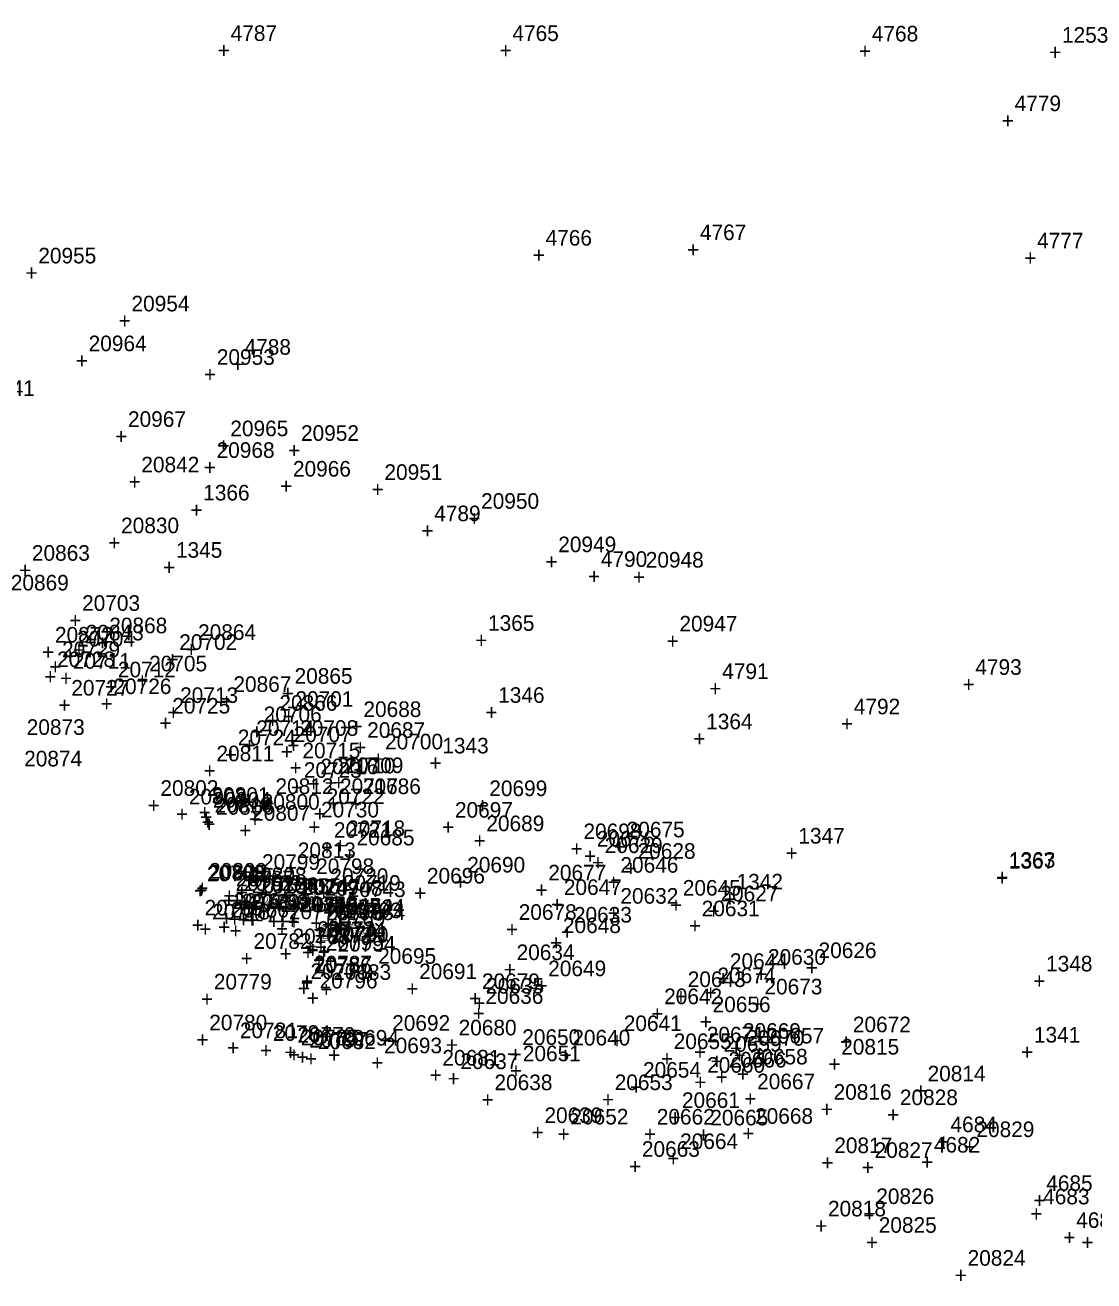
# Model space of a CAD drawing. Extents: x 1036751 to 1042192, y 772604 to 785439.
# Drawn here: x 1037673.8 to 1037845.1, y 780539.3 to 780740.6 of the extents above; entities that cross this region are included whole.
import ezdxf

# ---------------------------------------------------------------- set-up
doc = ezdxf.new("R2010")
doc.units = 0
for name, color, linetype in [('S_Buildings', 7, 'Continuous'), ('S_Buildings_Attachments', 7, 'Continuous'), ('S_Buildings_SillElevation', 7, 'Continuous'), ('S_Buildings_Steps_Brick', 7, 'Continuous'), ('S_Ground_Elevation', 7, 'Continuous'), ('S_Ground_LevelString', 7, 'Continuous'), ('S_Property_FlagPole', 7, 'Continuous'), ('S_Property_Lawn', 7, 'Continuous'), ('S_Property_Light', 7, 'Continuous'), ('S_Property_Mailbox', 7, 'Continuous'), ('S_Property_Planter', 7, 'Continuous'), ('S_Property_StoneWall', 7, 'Continuous'), ('S_RetWall_Top', 7, 'Continuous'), ('S_Roadway_Centerline', 7, 'Continuous'), ('S_Roadway_Drive_Paved', 7, 'Continuous'), ('S_Roadway_Edge_Pavement', 7, 'Continuous'), ('S_Trees_Stump', 7, 'Continuous'), ('S_Trees_TreeLine', 7, 'Continuous'), ('S_Utilities_Pole_Brace3', 7, 'Continuous'), ('S_Utilities_Pole_Power', 7, 'Continuous')]:
    doc.layers.add(name, color=color, linetype=linetype)

msp = doc.modelspace()

# ---------------------------------------------------------------- texts
at = {"layer": 'S_Buildings'}
for s, p in [('20803', (1037700.03, 780615.67)), ('20804', (1037703.89, 780615.16)), ('+', (1037697.96, 780612.92)), ('+', (1037701.83, 780612.41)), ('20805', (1037703.15, 780603.46)), ('+', (1037701.08, 780600.71))]:
    msp.add_text(s, height=2.5, dxfattribs=at).set_placement(p)
at = {"layer": 'S_Buildings_Attachments'}
for s, p in [('20768', (1037702.93, 780603.35)), ('20767', (1037707.59, 780602.54)), ('+', (1037700.87, 780600.6)), ('+', (1037705.53, 780599.79)), ('20765', (1037702.54, 780597.87)), ('20766', (1037706.77, 780597.54)), ('+', (1037700.48, 780595.12)), ('+', (1037704.71, 780594.79))]:
    msp.add_text(s, height=2.5, dxfattribs=at).set_placement(p)
at = {"layer": 'S_Buildings_SillElevation'}
for s, p in [('20810', (1037704.15, 780614.36)), ('+', (1037702.09, 780611.61))]:
    msp.add_text(s, height=2.5, dxfattribs=at).set_placement(p)
at = {"layer": 'S_Buildings_Steps_Brick'}
for s, p in [('20762', (1037707.52, 780601.81)), ('20763', (1037708.85, 780601.81)), ('20764', (1037710.08, 780601.42)), ('20756', (1037711.5, 780601.48)), ('20754', (1037711.52, 780601.39)), ('20755', (1037715.11, 780601.34)), ('20749', (1037717.99, 780601.14)), ('20747', (1037718.25, 780601.21)), ('20748', (1037721.79, 780601.02)), ('20743', (1037725.49, 780600.82)), ('+', (1037705.46, 780599.06)), ('+', (1037706.79, 780599.06)), ('20761', (1037707.15, 780598.93)), ('+', (1037708.02, 780598.67)), ('20760', (1037708.45, 780598.83)), ('+', (1037709.44, 780598.73)), ('+', (1037709.46, 780598.64)), ('20759', (1037709.88, 780598.78)), ('20758', (1037709.89, 780598.73)), ('20757', (1037711.26, 780598.69)), ('20753', (1037711.38, 780598.66)), ('+', (1037713.05, 780598.59)), ('20752', (1037714.73, 780598.43)), ('+', (1037716.19, 780598.46)), ('20751', (1037716.21, 780598.44)), ('20750', (1037717.7, 780598.46)), ('20746', (1037717.97, 780598.35)), ('20745', (1037721.55, 780598.16)), ('+', (1037715.93, 780598.39)), ('+', (1037719.73, 780598.28)), ('+', (1037723.43, 780598.07)), ('20744', (1037725.31, 780598.01)), ('+', (1037705.09, 780596.18)), ('+', (1037706.39, 780596.08)), ('+', (1037707.82, 780596.03)), ('+', (1037707.83, 780595.98)), ('+', (1037709.2, 780595.94)), ('+', (1037709.32, 780595.91)), ('+', (1037712.67, 780595.68)), ('+', (1037714.15, 780595.69)), ('+', (1037715.64, 780595.71)), ('+', (1037715.91, 780595.6)), ('+', (1037719.49, 780595.41)), ('+', (1037723.25, 780595.26))]:
    msp.add_text(s, height=2.5, dxfattribs=at).set_placement(p)
at = {"layer": 'S_Ground_Elevation'}
for s, p in [('4787', (1037706.73, 780738.07)), ('4765', (1037751.91, 780738.06)), ('4768', (1037809.54, 780737.99)), ('+', (1037704.67, 780735.32)), ('+', (1037749.85, 780735.31)), ('+', (1037807.48, 780735.24)), ('4779', (1037832.44, 780726.82)), ('+', (1037830.38, 780724.07)), ('4766', (1037757.23, 780705.26)), ('4767', (1037781.97, 780706.14)), ('4777', (1037836.04, 780704.81)), ('+', (1037779.91, 780703.39)), ('+', (1037755.17, 780702.51)), ('+', (1037833.98, 780702.06)), ('20964', (1037683.96, 780688.33)), ('4788', (1037708.96, 780687.77)), ('+', (1037681.9, 780685.58)), ('+', (1037706.9, 780685.02)), ('20965', (1037706.68, 780674.7)), ('20968', (1037704.48, 780671.23)), ('+', (1037704.62, 780671.95)), ('+', (1037702.42, 780668.48)), ('20966', (1037716.72, 780668.23)), ('+', (1037714.66, 780665.48)), ('4789', (1037739.37, 780661.08)), ('+', (1037737.31, 780658.33)), ('4790', (1037766.09, 780653.75)), ('+', (1037764.03, 780651)), ('20872', (1037678.56, 780641.62)), ('20704', (1037682.09, 780640.99)), ('+', (1037676.5, 780638.87)), ('20729', (1037679.7, 780639.28)), ('20728', (1037678.9, 780637.69)), ('+', (1037680.02, 780638.24)), ('20705', (1037693.66, 780637.01)), ('4793', (1037826.14, 780636.45)), ('+', (1037676.84, 780634.94)), ('+', (1037677.63, 780636.53)), ('4791', (1037785.55, 780635.77)), ('20727', (1037681.18, 780633.12)), ('20726', (1037687.94, 780633.36)), ('+', (1037691.6, 780634.26)), ('+', (1037783.48, 780633.02)), ('+', (1037824.08, 780633.7)), ('20725', (1037697.37, 780630.24)), ('+', (1037679.11, 780630.37)), ('+', (1037685.88, 780630.61)), ('20706', (1037712.03, 780628.86)), ('4792', (1037806.65, 780630.12)), ('20873', (1037674.03, 780626.82)), ('+', (1037695.31, 780627.49)), ('+', (1037804.59, 780627.37)), ('20724', (1037707.88, 780625.16)), ('+', (1037709.96, 780626.11)), ('20707', (1037716.83, 780625.66)), ('20811', (1037704.45, 780622.59)), ('+', (1037714.77, 780622.91)), ('20874', (1037673.62, 780621.77)), ('+', (1037705.82, 780622.41)), ('+', (1037702.39, 780619.84)), ('20723', (1037718.46, 780619.94)), ('20802', (1037695.47, 780617.05)), ('20812', (1037713.92, 780617.35)), ('+', (1037716.39, 780617.19)), ('20801', (1037703.66, 780615.92)), ('20800', (1037711.71, 780614.83)), ('+', (1037711.86, 780614.6)), ('20722', (1037722.12, 780615.72)), ('+', (1037693.41, 780614.3)), ('+', (1037701.6, 780613.17)), ('+', (1037720.06, 780612.97)), ('+', (1037709.65, 780612.08)), ('20721', (1037723.28, 780610.32)), ('20813', (1037717.5, 780607.07)), ('+', (1037721.21, 780607.57)), ('20629', (1037766.71, 780607.88)), ('20628', (1037771.98, 780606.96)), ('20799', (1037711.76, 780605.19)), ('20798', (1037720.44, 780604.52)), ('+', (1037764.65, 780605.13)), ('20646', (1037769.23, 780604.73)), ('+', (1037715.43, 780604.32)), ('20720', (1037722.72, 780602.93)), ('+', (1037769.91, 780604.21)), ('+', (1037709.7, 780602.44)), ('+', (1037718.38, 780601.77)), ('20647', (1037760.16, 780601.16)), ('+', (1037767.17, 780601.98)), ('20645', (1037779.23, 780601.05)), ('20627', (1037785.26, 780600.12)), ('+', (1037720.66, 780600.18)), ('20778', (1037703.75, 780597.23)), ('20777', (1037708.63, 780596.94)), ('20776', (1037716.06, 780597.26)), ('20775', (1037722.04, 780597.1)), ('20793', (1037724.87, 780597.44)), ('+', (1037758.1, 780598.41)), ('+', (1037777.17, 780598.3)), ('+', (1037783.2, 780597.37)), ('+', (1037701.69, 780594.48)), ('+', (1037714, 780594.51)), ('20773', (1037720.63, 780594.44)), ('20774', (1037722.3, 780594.34)), ('+', (1037722.8, 780594.69)), ('20648', (1037760.01, 780595.04)), ('+', (1037706.57, 780594.19)), ('20782', (1037710.39, 780592.52)), ('20783', (1037716.65, 780593.26)), ('+', (1037719.98, 780594.35)), ('20772', (1037720.21, 780593.47)), ('20795', (1037721.99, 780592.25)), ('20794', (1037723.86, 780592.08)), ('+', (1037714.59, 780590.51)), ('+', (1037718.15, 780590.72)), ('+', (1037718.57, 780591.69)), ('+', (1037720.24, 780591.59)), ('+', (1037757.95, 780592.29)), ('20626', (1037801, 780591.04)), ('+', (1037708.33, 780589.77)), ('+', (1037719.93, 780589.5)), ('+', (1037721.8, 780589.33)), ('20649', (1037757.65, 780588.13)), ('20644', (1037786.78, 780589.3)), ('20779', (1037704.03, 780586.01)), ('20771', (1037719.54, 780587.69)), ('20796', (1037720.99, 780586.17)), ('20643', (1037780.02, 780586.4)), ('+', (1037784.72, 780586.55)), ('20674', (1037784.79, 780587.01)), ('+', (1037798.94, 780588.29)), ('+', (1037717.48, 780584.94)), ('+', (1037755.59, 780585.38)), ('20673', (1037792.32, 780585.22)), ('+', (1037701.97, 780583.26)), ('+', (1037718.93, 780583.42)), ('20636', (1037747.58, 780583.7)), ('20642', (1037776.24, 780583.65)), ('+', (1037777.96, 780583.65)), ('+', (1037782.73, 780584.26)), ('20656', (1037784.01, 780582.36)), ('+', (1037790.26, 780582.47)), ('+', (1037745.52, 780580.95)), ('+', (1037774.18, 780580.9)), ('20780', (1037703.3, 780579.46)), ('20781', (1037708.21, 780578.2)), ('20641', (1037769.76, 780579.34)), ('+', (1037781.95, 780579.61)), ('20672', (1037806.5, 780579.15)), ('+', (1037701.24, 780576.71)), ('20784', (1037713.49, 780577.77)), ('20770', (1037717.43, 780577.47)), ('20797', (1037719.34, 780576.7)), ('20650', (1037753.49, 780577.12)), ('20640', (1037761.51, 780577.03)), ('+', (1037767.7, 780576.59)), ('20655', (1037777.77, 780576.45)), ('20659', (1037785.78, 780576.03)), ('20657', (1037792.59, 780577.35)), ('+', (1037804.44, 780576.4)), ('+', (1037706.15, 780575.45)), ('+', (1037711.43, 780575.02)), ('+', (1037715.36, 780574.72)), ('+', (1037751.43, 780574.37)), ('20651', (1037753.58, 780574.5)), ('20658', (1037789.96, 780573.99)), ('+', (1037790.53, 780574.6)), ('20815', (1037804.63, 780575.57)), ('+', (1037717.28, 780573.95)), ('20637', (1037743.57, 780573.25)), ('+', (1037759.45, 780574.28)), ('20654', (1037772.85, 780571.87)), ('+', (1037775.71, 780573.7)), ('20660', (1037783.13, 780572.66)), ('+', (1037783.72, 780573.28)), ('20666', (1037786.56, 780573.49)), ('+', (1037802.57, 780572.82)), ('+', (1037741.5, 780570.5)), ('20638', (1037749.03, 780569.86)), ('+', (1037751.52, 780571.75)), ('20653', (1037768.31, 780569.88)), ('+', (1037784.5, 780570.74)), ('+', (1037787.89, 780571.24)), ('20667', (1037791.15, 780570.01)), ('20814', (1037818.48, 780571.28)), ('+', (1037770.78, 780569.12)), ('+', (1037781.07, 780569.91)), ('20816', (1037803.41, 780568.33)), ('+', (1037816.42, 780568.53)), ('+', (1037746.97, 780567.11)), ('+', (1037766.25, 780567.13)), ('20661', (1037779.09, 780567.01)), ('+', (1037789.09, 780567.26)), ('20828', (1037814.04, 780567.46)), ('20639', (1037757.05, 780564.6)), ('20652', (1037761.21, 780564.37)), ('20662', (1037775.06, 780564.35)), ('+', (1037777.03, 780564.26)), ('20665', (1037783.64, 780564.22)), ('20668', (1037790.82, 780564.47)), ('+', (1037801.35, 780565.58)), ('+', (1037811.98, 780564.71)), ('4684', (1037822.15, 780563.12)), ('20829', (1037826.31, 780562.34)), ('+', (1037754.99, 780561.85)), ('+', (1037759.15, 780561.62)), ('+', (1037773, 780561.6)), ('20664', (1037778.8, 780560.43)), ('+', (1037781.58, 780561.47)), ('+', (1037788.76, 780561.72)), ('20817', (1037803.52, 780559.77)), ('4682', (1037819.49, 780559.86)), ('+', (1037820.09, 780560.37)), ('20663', (1037772.67, 780559.18)), ('20827', (1037809.99, 780559)), ('+', (1037824.24, 780559.59)), ('+', (1037770.61, 780556.43)), ('+', (1037776.74, 780557.68)), ('+', (1037801.46, 780557.02)), ('+', (1037807.93, 780556.25)), ('+', (1037817.43, 780557.11)), ('4685', (1037837.51, 780553.71)), ('20826', (1037810.25, 780551.61)), ('+', (1037835.45, 780550.96)), ('4683', (1037837.01, 780551.56)), ('20818', (1037802.51, 780549.63)), ('+', (1037808.19, 780548.86)), ('+', (1037834.95, 780548.81)), ('4686', (1037842.31, 780547.78)), ('+', (1037800.45, 780546.88)), ('20825', (1037810.65, 780547)), ('+', (1037808.58, 780544.25)), ('+', (1037840.25, 780545.03)), ('20824', (1037824.9, 780541.72)), ('+', (1037822.83, 780538.97))]:
    msp.add_text(s, height=2.5, dxfattribs=at).set_placement(p)
at = {"layer": 'S_Ground_LevelString'}
for s, p in [('20863', (1037674.86, 780654.74)), ('+', (1037672.8, 780651.99)), ('20869', (1037671.48, 780649.97)), ('20703', (1037682.91, 780646.71)), ('+', (1037680.85, 780643.96)), ('20868', (1037687.27, 780643.11)), ('20702', (1037698.48, 780640.45)), ('20864', (1037701.51, 780642.05)), ('+', (1037685.21, 780640.36)), ('+', (1037699.45, 780639.3)), ('+', (1037696.42, 780637.7)), ('20865', (1037716.98, 780635.02)), ('20867', (1037707.17, 780633.71)), ('+', (1037705.11, 780630.96)), ('20866', (1037714.55, 780630.69)), ('+', (1037714.92, 780632.27)), ('20701', (1037717.11, 780631.32)), ('+', (1037712.49, 780627.94)), ('+', (1037715.05, 780628.57)), ('20708', (1037717.88, 780626.67)), ('20700', (1037731.49, 780624.5)), ('+', (1037715.82, 780623.92)), ('20709', (1037725.13, 780620.7)), ('+', (1037729.43, 780621.75)), ('+', (1037723.07, 780617.95)), ('20699', (1037748.2, 780617.01)), ('20697', (1037742.69, 780613.55)), ('+', (1037746.14, 780614.26)), ('+', (1037740.63, 780610.8)), ('20689', (1037747.73, 780611.38)), ('20698', (1037763.3, 780610.11)), ('+', (1037745.67, 780608.64)), ('+', (1037761.24, 780607.36)), ('20690', (1037744.66, 780604.75)), ('1367', (1037831.5, 780605.38)), ('20696', (1037738.2, 780602.99)), ('+', (1037829.43, 780602.63)), ('+', (1037742.6, 780602)), ('+', (1037736.14, 780600.24)), ('20695', (1037730.38, 780590.13)), ('+', (1037728.32, 780587.38)), ('20691', (1037736.95, 780587.66)), ('+', (1037734.89, 780584.91)), ('20692', (1037732.63, 780579.39)), ('20694', (1037724.42, 780577.01)), ('+', (1037730.57, 780576.64)), ('20693', (1037731.33, 780575.78)), ('+', (1037722.36, 780574.26)), ('+', (1037729.27, 780573.03))]:
    msp.add_text(s, height=2.5, dxfattribs=at).set_placement(p)
at = {"layer": 'S_Property_FlagPole'}
for s, p in [('20730', (1037721.22, 780613.59)), ('+', (1037719.16, 780610.84))]:
    msp.add_text(s, height=2.5, dxfattribs=at).set_placement(p)
at = {"layer": 'S_Property_Lawn'}
for s, p in [('20632', (1037769.22, 780599.76)), ('20633', (1037761.77, 780596.73)), ('+', (1037767.16, 780597.01)), ('20631', (1037782.26, 780597.74)), ('+', (1037780.2, 780594.99)), ('+', (1037759.71, 780593.98)), ('20634', (1037752.58, 780590.72)), ('20630', (1037792.89, 780589.98)), ('+', (1037750.52, 780587.97)), ('+', (1037790.83, 780587.23)), ('20635', (1037747.69, 780585.34)), ('+', (1037745.63, 780582.59))]:
    msp.add_text(s, height=2.5, dxfattribs=at).set_placement(p)
at = {"layer": 'S_Property_Light'}
for s, p in [('20769', (1037722.24, 780596.16)), ('+', (1037720.18, 780593.41))]:
    msp.add_text(s, height=2.5, dxfattribs=at).set_placement(p)
at = {"layer": 'S_Property_Mailbox'}
for s, p in [('20710', (1037723.86, 780620.65)), ('+', (1037721.79, 780617.9))]:
    msp.add_text(s, height=2.5, dxfattribs=at).set_placement(p)
at = {"layer": 'S_Property_Planter'}
for s, p in [('20806', (1037704.38, 780614.03)), ('20807', (1037710.17, 780613.05)), ('+', (1037702.32, 780611.28)), ('+', (1037708.11, 780610.3)), ('20809', (1037703.27, 780603.78)), ('20808', (1037709.61, 780603.09)), ('+', (1037701.21, 780601.03)), ('+', (1037707.55, 780600.34))]:
    msp.add_text(s, height=2.5, dxfattribs=at).set_placement(p)
at = {"layer": 'S_Property_StoneWall'}
for s, p in [('20711', (1037681.42, 780637.43)), ('20712', (1037688.65, 780636.05)), ('+', (1037679.36, 780634.68)), ('+', (1037686.59, 780633.3)), ('20713', (1037698.63, 780631.94)), ('+', (1037696.57, 780629.19)), ('20714', (1037710.83, 780626.65)), ('+', (1037708.77, 780623.9)), ('20715', (1037718.24, 780623.07)), ('20716', (1037721.12, 780620.51)), ('+', (1037716.18, 780620.32)), ('+', (1037719.06, 780617.76)), ('20717', (1037724.27, 780617.35)), ('+', (1037722.21, 780614.6)), ('20718', (1037725.41, 780610.6)), ('+', (1037723.34, 780607.85)), ('20719', (1037724.71, 780601.84)), ('+', (1037722.65, 780599.09))]:
    msp.add_text(s, height=2.5, dxfattribs=at).set_placement(p)
at = {"layer": 'S_RetWall_Top'}
for s, p in [('20792', (1037723.45, 780597.92)), ('+', (1037721.39, 780595.17)), ('20788', (1037720.97, 780593.81)), ('20789', (1037720.98, 780593.93)), ('20790', (1037722.74, 780593.53)), ('20791', (1037722.85, 780593.7)), ('+', (1037718.91, 780591.06)), ('+', (1037718.92, 780591.18)), ('+', (1037720.68, 780590.78)), ('+', (1037720.79, 780590.95)), ('20786', (1037720.04, 780588.61)), ('20787', (1037720.09, 780588.9)), ('+', (1037717.98, 780585.86)), ('+', (1037718.02, 780586.15)), ('20785', (1037717.98, 780577.07)), ('+', (1037715.91, 780574.32))]:
    msp.add_text(s, height=2.5, dxfattribs=at).set_placement(p)
at = {"layer": 'S_Roadway_Centerline'}
for s, p in [('20830', (1037689.16, 780659.15)), ('+', (1037687.1, 780656.4)), ('1345', (1037697.96, 780655.22)), ('+', (1037695.9, 780652.47)), ('1346', (1037749.63, 780631.96)), ('+', (1037747.57, 780629.21)), ('1347', (1037797.76, 780609.4)), ('+', (1037795.7, 780606.65)), ('1348', (1037837.48, 780588.9)), ('+', (1037835.42, 780586.15))]:
    msp.add_text(s, height=2.5, dxfattribs=at).set_placement(p)
at = {"layer": 'S_Roadway_Drive_Paved'}
for s, p in [('20688', (1037728.02, 780629.69)), ('+', (1037725.96, 780626.94)), ('20687', (1037728.62, 780626.35)), ('+', (1037726.56, 780623.6)), ('20686', (1037727.93, 780617.33)), ('+', (1037725.86, 780614.58)), ('20675', (1037770.23, 780610.4)), ('20685', (1037726.91, 780609.11)), ('20676', (1037765.45, 780608.92)), ('+', (1037768.17, 780607.65)), ('+', (1037724.85, 780606.36)), ('+', (1037763.39, 780606.17)), ('20677', (1037757.66, 780603.49)), ('+', (1037755.6, 780600.74)), ('20684', (1037725.43, 780597.14)), ('20678', (1037752.92, 780597.17)), ('+', (1037723.36, 780594.39)), ('+', (1037750.86, 780594.42)), ('20683', (1037723.17, 780587.55)), ('20679', (1037747.02, 780586.08)), ('+', (1037721.11, 780584.8)), ('+', (1037744.96, 780583.33)), ('20680', (1037743.28, 780578.65)), ('20682', (1037720.71, 780576.44)), ('+', (1037741.22, 780575.9)), ('+', (1037718.65, 780573.69)), ('20681', (1037740.68, 780573.81)), ('+', (1037738.62, 780571.06))]:
    msp.add_text(s, height=2.5, dxfattribs=at).set_placement(p)
at = {"layer": 'S_Roadway_Edge_Pavement'}
for s, p in [('1253', (1037840.03, 780737.79)), ('+', (1037837.97, 780735.04)), ('20841', (1037666.02, 780681.16)), ('20842', (1037692.41, 780668.91)), ('+', (1037690.35, 780666.16)), ('1366', (1037702.33, 780664.4)), ('+', (1037700.27, 780661.65)), ('1365', (1037748, 780643.51)), ('20843', (1037683.5, 780641.97)), ('+', (1037745.94, 780640.77)), ('+', (1037681.44, 780639.22)), ('1364', (1037782.98, 780627.72)), ('+', (1037780.92, 780624.97)), ('1343', (1037740.67, 780623.85)), ('+', (1037738.61, 780621.1)), ('1363', (1037831.54, 780605.52)), ('1342', (1037787.85, 780602.04)), ('+', (1037829.48, 780602.77)), ('+', (1037785.79, 780599.29)), ('1341', (1037835.53, 780577.5)), ('+', (1037833.47, 780574.75))]:
    msp.add_text(s, height=2.5, dxfattribs=at).set_placement(p)
at = {"layer": 'S_Trees_Stump'}
for s, p in [('20669', (1037788.87, 780578.11)), ('20671', (1037783.08, 780577.52)), ('20670', (1037789.44, 780576.99)), ('+', (1037781.02, 780574.77)), ('+', (1037786.81, 780575.36)), ('+', (1037787.38, 780574.24))]:
    msp.add_text(s, height=2.5, dxfattribs=at).set_placement(p)
at = {"layer": 'S_Trees_TreeLine'}
for s, p in [('20955', (1037675.89, 780702.41)), ('+', (1037673.82, 780699.66)), ('20954', (1037690.83, 780694.72)), ('+', (1037688.76, 780691.97)), ('20953', (1037704.51, 780686.15)), ('+', (1037702.44, 780683.4)), ('20952', (1037718.01, 780673.96)), ('+', (1037715.95, 780671.21)), ('20951', (1037731.39, 780667.7)), ('+', (1037729.33, 780664.95)), ('20950', (1037746.89, 780663.07)), ('+', (1037744.83, 780660.32)), ('20949', (1037759.26, 780656.11)), ('+', (1037757.2, 780653.36)), ('20948', (1037773.29, 780653.64)), ('+', (1037771.23, 780650.89)), ('20947', (1037778.69, 780643.4)), ('+', (1037776.63, 780640.65))]:
    msp.add_text(s, height=2.5, dxfattribs=at).set_placement(p)
at = {"layer": 'S_Utilities_Pole_Brace3'}
msp.add_text('+', height=2.5, dxfattribs=at).set_placement((1037843.14, 780544.25))
at = {"layer": 'S_Utilities_Pole_Power'}
for s, p in [('20967', (1037690.27, 780676.2)), ('+', (1037688.21, 780673.45))]:
    msp.add_text(s, height=2.5, dxfattribs=at).set_placement(p)

doc.saveas('drawing.dxf')
